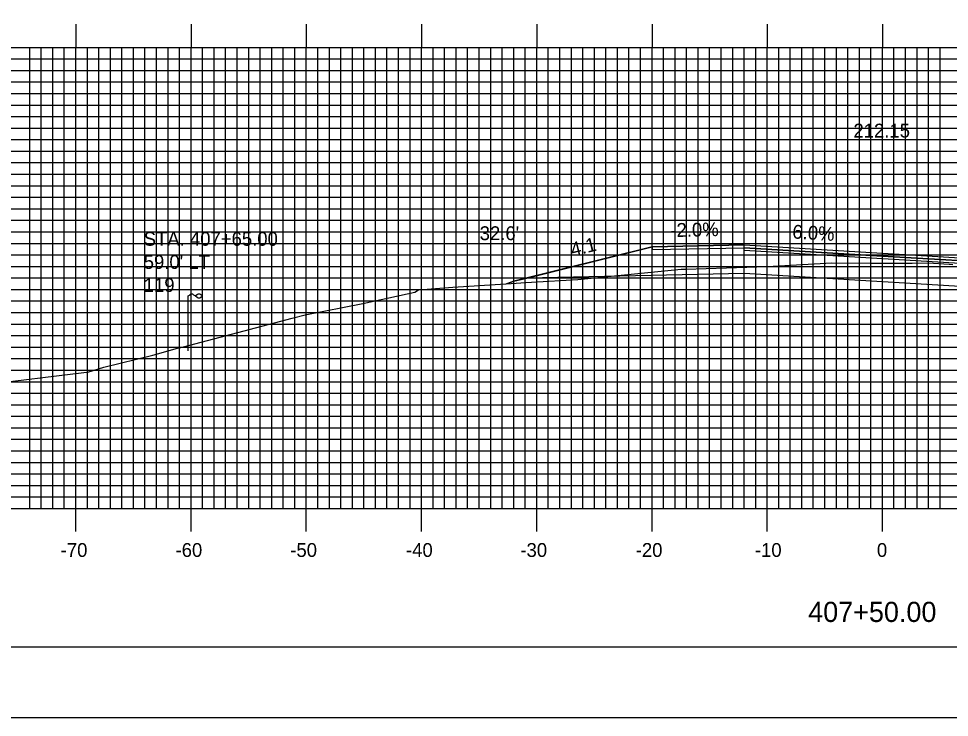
# Model space of a CAD drawing. Extents: x 852529 to 852872, y 364785 to 365005.
# Drawn here: x 852619.8 to 852700.5, y 364785.1 to 364845.7 of the extents above; entities that cross this region are included whole.
import ezdxf

# ---------------------------------------------------------------- set-up
doc = ezdxf.new("R2010")
doc.units = 0
for name, color, linetype in [('ANNOTATION', 7, 'Continuous'), ('BORDER', 7, 'Continuous'), ('D_Drainage_Text', 7, 'Continuous'), ('D_Roadway_Centerline', 7, 'Continuous'), ('D_Roadway_Centerline_Text', 7, 'Continuous'), ('D_Roadway_Edge_Shoulder', 7, 'Continuous'), ('D_Roadway_Edge_TW', 7, 'Continuous'), ('D_Roadway_Pavement', 7, 'Continuous'), ('D_Roadway_SlopeLines', 7, 'Continuous'), ('D_Roadway_SubGrade', 7, 'Continuous'), ('D_Text_Standard', 7, 'Continuous'), ('D_Utilities_Pole_Joint', 7, 'Continuous'), ('H_V ANNOTATION', 7, 'Continuous'), ('MAJOR', 7, 'Continuous'), ('MINOR', 7, 'Continuous'), ('PLOT BOUNDARY', 7, 'Continuous'), ('S_Roadway_Centerline', 7, 'Continuous')]:
    doc.layers.add(name, color=color, linetype=linetype)

msp = doc.modelspace()

# ---------------------------------------------------------------- linework, layer by layer
at = {"layer": 'BORDER'}
msp.add_lwpolyline([(852545.131, 364791.233), (852865.131, 364791.233), (852865.131, 365001.233), (852545.131, 365001.233)], close=True, dxfattribs=at)
at = {"layer": 'D_Roadway_Centerline'}
msp.add_lwpolyline([(852662.106, 364822.735), (852662.731, 364822.943), (852663.861, 364823.226), (852674.731, 364825.943), (852682.731, 364826.103), (852694.731, 364825.383), (852706.731, 364824.663), (852714.731, 364824.183), (852727.889, 364820.894), (852731.889, 364819.894), (852738.007, 364822.953), (852739.257, 364823.515), (852740.507, 364823.951), (852741.757, 364824.261), (852743.007, 364824.445)], dxfattribs=at)
at = {"layer": 'D_Roadway_Edge_Shoulder'}
msp.add_lwpolyline([(852682.731, 364826.103), (852674.731, 364825.943), (852674.731, 364825.693), (852682.731, 364825.853)], close=True, dxfattribs=at)
at = {"layer": 'D_Roadway_Edge_TW'}
msp.add_lwpolyline([(852682.731, 364825.853), (852682.731, 364826.103), (852694.731, 364825.383), (852706.731, 364824.663), (852706.731, 364824.413), (852694.731, 364825.133)], close=True, dxfattribs=at)
at = {"layer": 'D_Roadway_Pavement'}
msp.add_lwpolyline([(852682.731, 364825.603), (852682.731, 364825.853), (852694.731, 364825.133), (852706.731, 364824.413), (852706.731, 364824.163), (852694.731, 364824.883)], close=True, dxfattribs=at)
at = {"layer": 'D_Roadway_SlopeLines'}
msp.add_lwpolyline([(852674.731, 364825.943), (852662.731, 364822.943), (852662.106, 364822.735)], dxfattribs=at)
at = {"layer": 'D_Roadway_SubGrade'}
msp.add_lwpolyline([(852682.731, 364823.603), (852663.861, 364823.226), (852674.731, 364825.943), (852674.731, 364825.693), (852682.731, 364825.853), (852694.731, 364825.133), (852706.731, 364824.413), (852714.731, 364823.933), (852714.731, 364824.183), (852727.889, 364820.894), (852706.731, 364822.163), (852694.731, 364822.883)], close=True, dxfattribs=at)
at = {"layer": 'D_Utilities_Pole_Joint'}
for p, q in [((852634.481, 364821.667), (852634.637, 364821.778)), ((852634.481, 364816.909), (852634.481, 364821.667)), ((852634.949, 364821.778), (852635.105, 364821.667)), ((852635.262, 364821.778), (852635.105, 364821.667)), ((852635.105, 364821.667), (852635.262, 364821.556)), ((852635.731, 364821.667), (852635.575, 364821.778)), ((852635.575, 364821.556), (852635.731, 364821.667)), ((852635.731, 364816.909), (852635.731, 364821.667))]:
    msp.add_line(p, q, dxfattribs=at)
for centre, start, end in [((852634.793, 364821.557), 90, 125.26439), ((852634.793, 364821.557), 54.73561, 90), ((852635.418, 364821.557), 90, 125.26439), ((852635.418, 364821.778), 234.73561, 270), ((852635.418, 364821.557), 54.73561, 90), ((852635.418, 364821.778), 270, 305.26439)]:
    msp.add_arc(centre, 0.271, start, end, dxfattribs=at)
at = {"layer": 'MAJOR'}
for p, q in [((852624.731, 364845.237), (852624.731, 364843.233)), ((852634.731, 364845.237), (852634.731, 364843.233)), ((852644.731, 364845.237), (852644.731, 364843.233)), ((852654.731, 364845.237), (852654.731, 364843.233)), ((852664.731, 364845.237), (852664.731, 364843.233)), ((852674.731, 364845.237), (852674.731, 364843.233)), ((852684.731, 364845.237), (852684.731, 364843.233)), ((852694.731, 364845.237), (852694.731, 364843.233)), ((852554.731, 364843.233), (852834.731, 364843.233)), ((852554.731, 364843.233), (852834.731, 364843.233)), ((852624.731, 364803.233), (852624.731, 364843.233)), ((852634.731, 364803.233), (852634.731, 364843.233)), ((852644.731, 364803.233), (852644.731, 364843.233)), ((852654.731, 364803.233), (852654.731, 364843.233)), ((852664.731, 364803.233), (852664.731, 364843.233)), ((852674.731, 364803.233), (852674.731, 364843.233)), ((852684.731, 364803.233), (852684.731, 364843.233)), ((852694.731, 364803.233), (852694.731, 364843.233)), ((852554.731, 364838.233), (852834.731, 364838.233)), ((852554.731, 364833.233), (852834.731, 364833.233)), ((852554.731, 364828.233), (852834.731, 364828.233)), ((852554.731, 364823.233), (852834.731, 364823.233)), ((852554.731, 364818.233), (852834.731, 364818.233)), ((852554.731, 364813.233), (852834.731, 364813.233)), ((852554.731, 364808.233), (852834.731, 364808.233)), ((852554.731, 364803.233), (852834.731, 364803.233)), ((852554.731, 364803.233), (852834.731, 364803.233)), ((852624.731, 364801.229), (852624.731, 364803.233)), ((852634.731, 364801.229), (852634.731, 364803.233)), ((852644.731, 364801.229), (852644.731, 364803.233)), ((852654.731, 364801.229), (852654.731, 364803.233)), ((852664.731, 364801.229), (852664.731, 364803.233)), ((852674.731, 364801.229), (852674.731, 364803.233)), ((852684.731, 364801.229), (852684.731, 364803.233)), ((852694.731, 364801.229), (852694.731, 364803.233))]:
    msp.add_line(p, q, dxfattribs=at)
at = {"layer": 'MINOR'}
for p, q in [((852620.731, 364803.233), (852620.731, 364843.233)), ((852621.731, 364803.233), (852621.731, 364843.233)), ((852622.731, 364803.233), (852622.731, 364843.233)), ((852623.731, 364803.233), (852623.731, 364843.233)), ((852625.731, 364803.233), (852625.731, 364843.233)), ((852626.731, 364803.233), (852626.731, 364843.233)), ((852627.731, 364803.233), (852627.731, 364843.233)), ((852628.731, 364803.233), (852628.731, 364843.233)), ((852629.731, 364803.233), (852629.731, 364843.233)), ((852630.731, 364803.233), (852630.731, 364843.233)), ((852631.731, 364803.233), (852631.731, 364843.233)), ((852632.731, 364803.233), (852632.731, 364843.233)), ((852633.731, 364803.233), (852633.731, 364843.233)), ((852635.731, 364803.233), (852635.731, 364843.233)), ((852636.731, 364803.233), (852636.731, 364843.233)), ((852637.731, 364803.233), (852637.731, 364843.233)), ((852638.731, 364803.233), (852638.731, 364843.233)), ((852639.731, 364803.233), (852639.731, 364843.233)), ((852640.731, 364803.233), (852640.731, 364843.233)), ((852641.731, 364803.233), (852641.731, 364843.233)), ((852642.731, 364803.233), (852642.731, 364843.233)), ((852643.731, 364803.233), (852643.731, 364843.233)), ((852645.731, 364803.233), (852645.731, 364843.233)), ((852646.731, 364803.233), (852646.731, 364843.233)), ((852647.731, 364803.233), (852647.731, 364843.233)), ((852648.731, 364803.233), (852648.731, 364843.233)), ((852649.731, 364803.233), (852649.731, 364843.233)), ((852650.731, 364803.233), (852650.731, 364843.233)), ((852651.731, 364803.233), (852651.731, 364843.233)), ((852652.731, 364803.233), (852652.731, 364843.233)), ((852653.731, 364803.233), (852653.731, 364843.233)), ((852655.731, 364803.233), (852655.731, 364843.233)), ((852656.731, 364803.233), (852656.731, 364843.233)), ((852657.731, 364803.233), (852657.731, 364843.233)), ((852658.731, 364803.233), (852658.731, 364843.233)), ((852659.731, 364803.233), (852659.731, 364843.233)), ((852660.731, 364803.233), (852660.731, 364843.233)), ((852661.731, 364803.233), (852661.731, 364843.233)), ((852662.731, 364803.233), (852662.731, 364843.233)), ((852663.731, 364803.233), (852663.731, 364843.233)), ((852665.731, 364803.233), (852665.731, 364843.233)), ((852666.731, 364803.233), (852666.731, 364843.233)), ((852667.731, 364803.233), (852667.731, 364843.233)), ((852668.731, 364803.233), (852668.731, 364843.233)), ((852669.731, 364803.233), (852669.731, 364843.233)), ((852670.731, 364803.233), (852670.731, 364843.233)), ((852671.731, 364803.233), (852671.731, 364843.233)), ((852672.731, 364803.233), (852672.731, 364843.233)), ((852673.731, 364803.233), (852673.731, 364843.233)), ((852675.731, 364803.233), (852675.731, 364843.233)), ((852676.731, 364803.233), (852676.731, 364843.233)), ((852677.731, 364803.233), (852677.731, 364843.233)), ((852678.731, 364803.233), (852678.731, 364843.233)), ((852679.731, 364803.233), (852679.731, 364843.233)), ((852680.731, 364803.233), (852680.731, 364843.233)), ((852681.731, 364803.233), (852681.731, 364843.233)), ((852682.731, 364803.233), (852682.731, 364843.233)), ((852683.731, 364803.233), (852683.731, 364843.233)), ((852685.731, 364803.233), (852685.731, 364843.233)), ((852686.731, 364803.233), (852686.731, 364843.233)), ((852687.731, 364803.233), (852687.731, 364843.233)), ((852688.731, 364803.233), (852688.731, 364843.233)), ((852689.731, 364803.233), (852689.731, 364843.233)), ((852690.731, 364803.233), (852690.731, 364843.233)), ((852691.731, 364803.233), (852691.731, 364843.233)), ((852692.731, 364803.233), (852692.731, 364843.233)), ((852693.731, 364803.233), (852693.731, 364843.233)), ((852695.731, 364803.233), (852695.731, 364843.233)), ((852696.731, 364803.233), (852696.731, 364843.233)), ((852697.731, 364803.233), (852697.731, 364843.233)), ((852698.731, 364803.233), (852698.731, 364843.233)), ((852699.731, 364803.233), (852699.731, 364843.233)), ((852554.731, 364842.233), (852834.731, 364842.233)), ((852554.731, 364841.233), (852834.731, 364841.233)), ((852554.731, 364840.233), (852834.731, 364840.233)), ((852554.731, 364839.233), (852834.731, 364839.233)), ((852554.731, 364837.233), (852834.731, 364837.233)), ((852554.731, 364836.233), (852834.731, 364836.233)), ((852554.731, 364835.233), (852834.731, 364835.233)), ((852554.731, 364834.233), (852834.731, 364834.233)), ((852554.731, 364832.233), (852834.731, 364832.233)), ((852554.731, 364831.233), (852834.731, 364831.233)), ((852554.731, 364830.233), (852834.731, 364830.233)), ((852554.731, 364829.233), (852834.731, 364829.233)), ((852554.731, 364827.233), (852834.731, 364827.233)), ((852554.731, 364826.233), (852834.731, 364826.233)), ((852554.731, 364825.233), (852834.731, 364825.233)), ((852554.731, 364824.233), (852834.731, 364824.233)), ((852554.731, 364822.233), (852834.731, 364822.233)), ((852554.731, 364821.233), (852834.731, 364821.233)), ((852554.731, 364820.233), (852834.731, 364820.233)), ((852554.731, 364819.233), (852834.731, 364819.233)), ((852554.731, 364817.233), (852834.731, 364817.233)), ((852554.731, 364816.233), (852834.731, 364816.233)), ((852554.731, 364815.233), (852834.731, 364815.233)), ((852554.731, 364814.233), (852834.731, 364814.233)), ((852554.731, 364812.233), (852834.731, 364812.233)), ((852554.731, 364811.233), (852834.731, 364811.233)), ((852554.731, 364810.233), (852834.731, 364810.233)), ((852554.731, 364809.233), (852834.731, 364809.233)), ((852554.731, 364807.233), (852834.731, 364807.233)), ((852554.731, 364806.233), (852834.731, 364806.233)), ((852554.731, 364805.233), (852834.731, 364805.233)), ((852554.731, 364804.233), (852834.731, 364804.233))]:
    msp.add_line(p, q, dxfattribs=at)
at = {"layer": 'PLOT BOUNDARY'}
msp.add_lwpolyline([(852528.944, 364785.114), (852868.944, 364785.114), (852868.944, 365005.114), (852528.944, 365005.114)], close=True, dxfattribs=at)
at = {"layer": 'S_Roadway_Centerline'}
msp.add_lwpolyline([(852616.863, 364813.998), (852625.428, 364815.017), (852625.758, 364815.055), (852627.166, 364815.481), (852631.4, 364816.546), (852633.539, 364817.127), (852633.848, 364817.211), (852634.061, 364817.253), (852643.496, 364819.735), (852644.63, 364820.038), (852649.642, 364821.026), (852654.156, 364822.001), (852654.465, 364822.201), (852656.322, 364822.337), (852657.446, 364822.436), (852662.5, 364822.76), (852663.767, 364822.828), (852664.259, 364822.871), (852668.303, 364823.096), (852677.268, 364823.987), (852677.369, 364823.996), (852677.676, 364824.004), (852684.717, 364824.239), (852690.341, 364824.546), (852693.7, 364824.514), (852697.307, 364824.51), (852698.711, 364824.557), (852700.526, 364824.42), (852700.838, 364824.392)], dxfattribs=at)

# ---------------------------------------------------------------- texts
at = {"layer": 'ANNOTATION'}
for s, rotation, p in [('-2.0%', 1.14576, (852676.337, 364826.776)), ('6.0%', 356.56637, (852686.885, 364826.658)), ('4:1', 14.03624, (852667.832, 364825.08))]:
    msp.add_text(s, height=1.2, rotation=rotation, dxfattribs=at).set_placement(p)
at = {"layer": 'D_Drainage_Text'}
for s, p in [('STA. 407+65.00', (852630.619, 364826.024)), ("59.0' LT", (852630.619, 364824.02)), ('119', (852630.619, 364822.016))]:
    msp.add_text(s, height=1.2, dxfattribs=at).set_placement(p)
at = {"layer": 'D_Roadway_Centerline'}
for s, p in [('C', (852694.725, 364825.383)), ('L', (852694.731, 364825.376))]:
    msp.add_text(s, height=0.0146, dxfattribs=at).set_placement(p)
at = {"layer": 'D_Roadway_Centerline_Text'}
msp.add_text('212.15', height=1.2, dxfattribs=at).set_placement((852692.211, 364835.413))
at = {"layer": 'D_Text_Standard'}
msp.add_text("32.6'", height=1.2, dxfattribs=at).set_placement((852659.776, 364826.512))
at = {"layer": 'H_V ANNOTATION'}
for s, height, p in [('-70', 1.2, (852623.414, 364799.033)), ('-60', 1.2, (852633.382, 364799.033)), ('-50', 1.2, (852643.339, 364799.033)), ('-40', 1.2, (852653.382, 364799.033)), ('-30', 1.2, (852663.307, 364799.033)), ('-20', 1.2, (852673.318, 364799.033)), ('-10', 1.2, (852683.66, 364799.033)), ('0', 1.2, (852694.249, 364799.033)), ('407+50.00', 1.75, (852688.285, 364793.389))]:
    msp.add_text(s, height=height, dxfattribs=at).set_placement(p)
at = {"layer": 'S_Roadway_Centerline'}
for s, p in [('L', (852677.36, 364823.989)), ('C', (852677.363, 364823.996))]:
    msp.add_text(s, height=0.0146, dxfattribs=at).set_placement(p)

doc.saveas('drawing.dxf')
